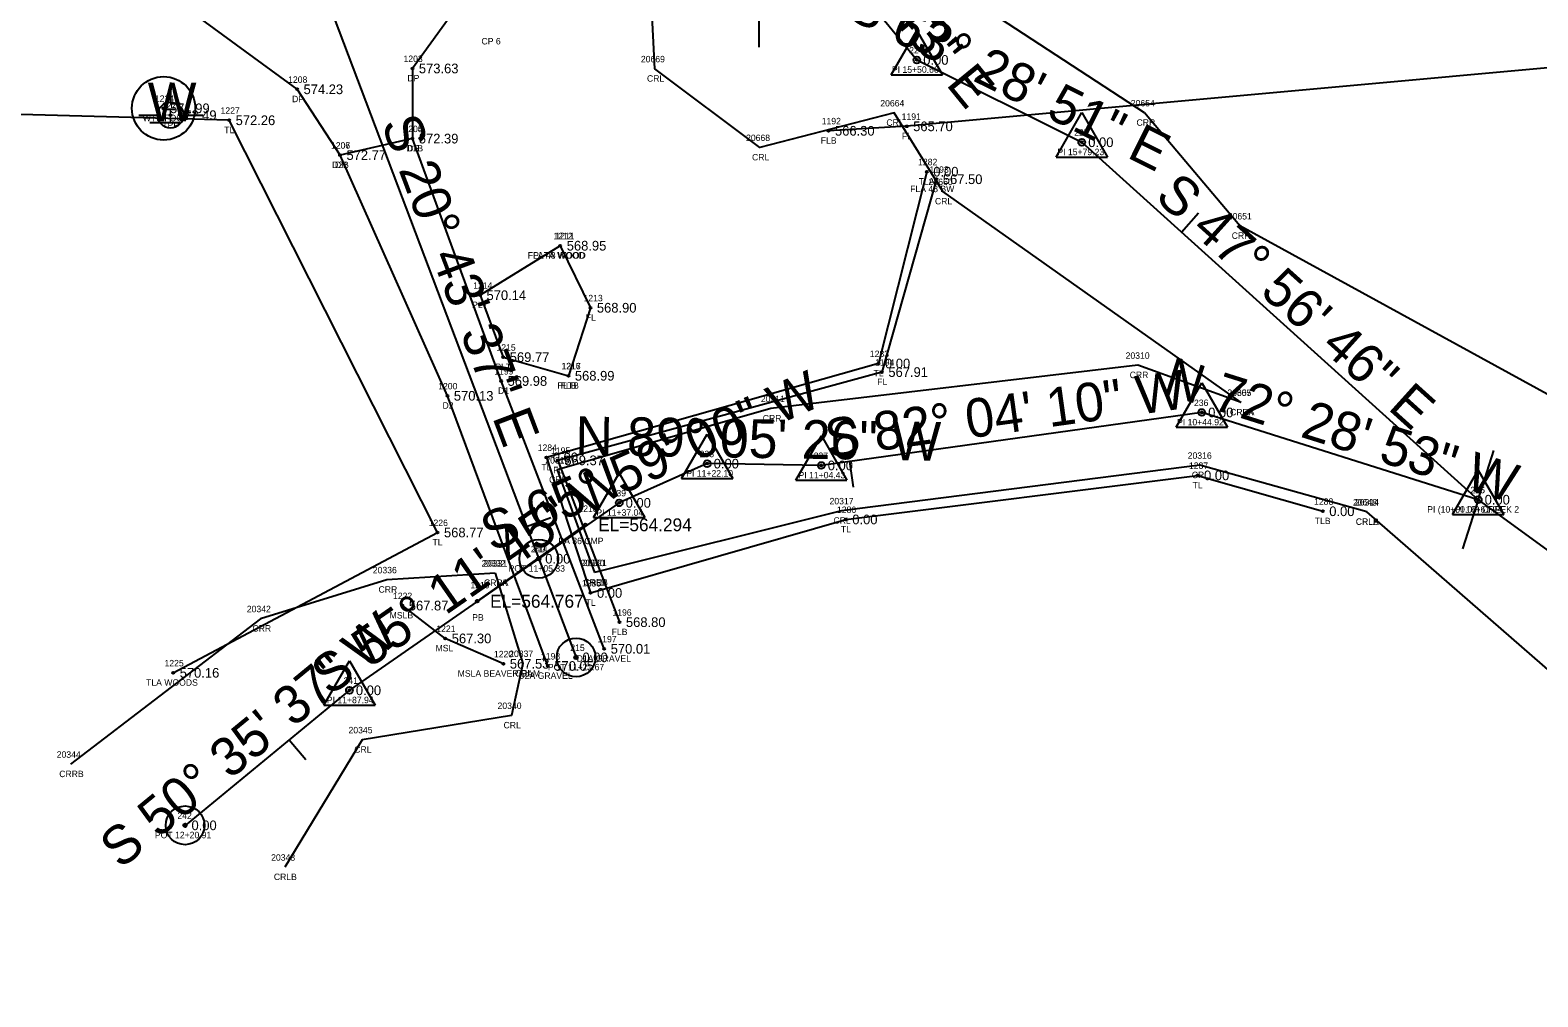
# Model space of a CAD drawing. Extents: x 1529475 to 1532053, y 876698 to 877911.
# Drawn here: x 1530784.5 to 1531018, y 877104.3 to 877254.2 of the extents above; entities that cross this region are included whole.
import ezdxf

# ---------------------------------------------------------------- set-up
doc = ezdxf.new("R2010")
doc.units = 0
for name, color, linetype in [('RD_EX_BldgApp', 7, 'Continuous'), ('RD_EX_BldgApp_txCode', 7, 'Continuous'), ('RD_EX_DR_Pipe', 7, 'Continuous'), ('RD_EX_DR_Pipe_txCode', 7, 'Continuous'), ('RD_EX_Driveway', 7, 'Continuous'), ('RD_EX_Driveway_txCode', 7, 'Continuous'), ('RD_EX_Fence_Other', 7, 'Continuous'), ('RD_EX_Fence_Other_txCode', 7, 'Continuous'), ('RD_EX_H2O', 7, 'Continuous'), ('RD_EX_H2O_txCode', 7, 'Continuous'), ('RD_EX_Misc', 7, 'Continuous'), ('RD_EX_Misc_txCode', 7, 'Continuous'), ('RD_EX_TX_BldgApp_ELEV', 7, 'Continuous'), ('RD_EX_TX_Driveway_ELEV', 7, 'Continuous'), ('RD_EX_TX_Fence_Other_ELEV', 7, 'Continuous'), ('RD_EX_TX_Misc_ELEV', 7, 'Continuous'), ('RD_EX_TX_UT_ELEV', 7, 'Continuous'), ('RD_EX_TX_VEG_ELEV', 7, 'Continuous'), ('RD_EX_UT', 7, 'Continuous'), ('RD_EX_UT_txCode', 7, 'Continuous'), ('RD_EX_VEG', 7, 'Continuous'), ('RD_EX_VEG_txCode', 7, 'Continuous'), ('RD_HC_Cl', 7, 'Continuous'), ('RD_HC_Data', 7, 'Continuous'), ('RD_HC_Data_Tic', 7, 'Continuous'), ('RD_HC_Survey_ELEV', 7, 'Continuous'), ('RD_HC_Survey_txCode', 7, 'Continuous'), ('RD_HC_txCode', 7, 'Continuous'), ('RD_SMD_Locator', 7, 'Continuous'), ('RD_TX_Pipe_ElevEX', 7, 'Continuous')]:
    doc.layers.add(name, color=color, linetype=linetype)

msp = doc.modelspace()

# ---------------------------------------------------------------- linework, layer by layer
at = {"layer": 'RD_EX_BldgApp'}
msp.add_lwpolyline([(1530866.59, 877220.77), (1530854.16, 877213.09), (1530857.76, 877203.5), (1530867.85, 877200.61)], dxfattribs=at)
at = {"layer": 'RD_EX_DR_Pipe'}
msp.add_line((1530870.46, 877177.51), (1530853.72, 877165.66), dxfattribs=at)
at = {"layer": 'RD_EX_Driveway'}
for points in [[(1530852.87, 877260.97), (1530843.68, 877248.24), (1530843.67, 877237.37), (1530832.46, 877234.81), (1530825.81, 877245.01), (1530806.23, 877259.4)], [(1530873.4, 877158.29), (1530857.42, 877199.8), (1530843.67, 877237.37)], [(1530864.66, 877155.63), (1530849.1, 877197.5), (1530832.46, 877234.81)]]:
    msp.add_lwpolyline(points, dxfattribs=at)
at = {"layer": 'RD_EX_Fence_Other'}
for points in [[(1531584.5, 877106.78), (1531547.82, 877137.37), (1531457.58, 877185.31), (1531406.02, 877209.64), (1531373.66, 877220.15), (1531357.95, 877224.14), (1531321.76, 877233.71), (1531272.23, 877245.59), (1531232.6, 877249.66), (1531180.73, 877254.11), (1531131.27, 877254.15), (1531075.59, 877251.89), (1531032.65, 877249.5), (1530920.26, 877239.27), (1530908.15, 877238.58)], [(1530924.86, 877231.07), (1530916.42, 877201.18), (1530866.22, 877187.5), (1530875.76, 877162.42)], [(1530866.59, 877220.77), (1530871.26, 877211.15), (1530867.85, 877200.61)]]:
    msp.add_lwpolyline(points, dxfattribs=at)
at = {"layer": 'RD_EX_H2O'}
msp.add_line((1530897.4, 877251.52), (1530897.4, 877261.52), dxfattribs=at)
for points in [[(1531030.35, 877191.82), (1530971.87, 877223.83), (1530957.12, 877241.36), (1530927.2, 877260.93), (1530922.5, 877289.86), (1530895.04, 877301.24), (1530872.88, 877333.85), (1530860.22, 877363.17), (1530828.43, 877393.28), (1530808.3, 877433.62), (1530784.24, 877462.07), (1530773.36, 877492.12), (1530746.47, 877535.88), (1530723.52, 877580.98), (1530706.2, 877619.34), (1530689.1, 877649.27), (1530633.62, 877702.51)], [(1530972.1, 877196.48), (1530925.87, 877229.17), (1530918.34, 877241.35), (1530897.53, 877235.99), (1530881.25, 877248.19), (1530880.72, 877258.4), (1530879.1, 877290.18), (1530865.94, 877309.23), (1530832.49, 877347.64), (1530816.44, 877373.18)], [(1530972.1, 877196.48), (1530956.06, 877202.24), (1530899.21, 877195.52), (1530866.11, 877186.01), (1530871.9, 877170.1)], [(1530991.55, 877179.5), (1530965.66, 877186.74), (1530910.14, 877179.68), (1530871.9, 877170.1)], [(1531352.2, 877088.06), (1531314.99, 877102.13), (1531274.47, 877089.9), (1531245.67, 877076.46), (1531215.61, 877089.16), (1531183.19, 877108.46), (1531131.31, 877133.17), (1531102.07, 877130.33), (1531078.17, 877119.78), (1531028.38, 877147.46), (1530991.55, 877179.5)], [(1530856.5, 877170.04), (1530839.69, 877168.99), (1530820.14, 877162.96), (1530790.69, 877140.4)], [(1530856.5, 877170.04), (1530860.79, 877156.02), (1530859.03, 877147.96), (1530835.9, 877144.19), (1530823.91, 877124.45)]]:
    msp.add_lwpolyline(points, dxfattribs=at)
at = {"layer": 'RD_EX_Misc'}
msp.add_lwpolyline([(1530857.77, 877155.97), (1530848.77, 877159.9), (1530842.12, 877164.99)], dxfattribs=at)
at = {"layer": 'RD_EX_UT'}
for p, q in [((1530806.2, 877246.07), (1530806.2, 877243)), ((1530801.27, 877241.01), (1530804.2, 877241.01)), ((1530808.2, 877241.01), (1530811.27, 877241.01)), ((1530803, 877239.85), (1530807.63, 877239.85))]:
    msp.add_line(p, q, dxfattribs=at)
for centre, radius in [((1530805.13, 877242.06), 4.91), ((1530806.2, 877241), 2)]:
    msp.add_circle(centre, radius, dxfattribs=at)
at = {"layer": 'RD_EX_VEG'}
for points in [[(1530806.62, 877154.57), (1530847.57, 877176.32), (1530815.29, 877240.21), (1530607.98, 877245.85), (1530502.71, 877258.91), (1530344.51, 877291.95), (1530315.54, 877291.5), (1530341.13, 877248.83)], [(1530923.38, 877232.24), (1530915.9, 877202.51), (1530864.43, 877187.96), (1530871.28, 877166.95), (1530910.83, 877178.34), (1530965.33, 877185.17), (1530984.73, 877179.61)]]:
    msp.add_lwpolyline(points, dxfattribs=at)
at = {"layer": 'RD_HC_Cl'}
for p, q in [((1530901.97, 877273.85), (1530921.83, 877249.56)), ((1530825.97, 877270.76), (1530869.03, 877156.96)), ((1530921.83, 877249.56), (1530947.39, 877236.8)), ((1530947.39, 877236.8), (1531008.81, 877181.4)), ((1530965.97, 877194.92), (1530907.03, 877186.71)), ((1531008.81, 877181.4), (1530965.97, 877194.92)), ((1530889.36, 877186.99), (1530875.72, 877180.91)), ((1530907.03, 877186.71), (1530889.36, 877186.99)), ((1530875.72, 877180.91), (1530833.92, 877151.86)), ((1531008.81, 877181.4), (1531075.6, 877132.71)), ((1530833.92, 877151.86), (1530808.45, 877130.93))]:
    msp.add_line(p, q, dxfattribs=at)
at = {"layer": 'RD_HC_Data'}
for p, q in [((1530917.86, 877247.26), (1530921.84, 877254.14)), ((1530921.84, 877254.14), (1530925.8, 877247.26)), ((1530917.86, 877247.26), (1530925.8, 877247.26)), ((1530943.42, 877234.51), (1530947.39, 877241.39)), ((1530947.39, 877241.39), (1530951.36, 877234.51)), ((1530943.42, 877234.51), (1530951.36, 877234.51)), ((1530962, 877192.63), (1530965.97, 877199.51)), ((1530965.97, 877199.51), (1530969.94, 877192.63)), ((1530962, 877192.63), (1530969.94, 877192.63)), ((1530885.39, 877184.7), (1530889.36, 877191.58)), ((1530889.36, 877191.58), (1530893.33, 877184.7)), ((1530903.06, 877184.42), (1530907.04, 877191.3)), ((1530907.04, 877191.3), (1530911, 877184.42)), ((1530871.75, 877178.62), (1530875.72, 877185.5)), ((1530875.72, 877185.5), (1530879.69, 877178.62)), ((1530885.39, 877184.7), (1530893.33, 877184.7)), ((1531004.84, 877179.11), (1531008.81, 877185.99)), ((1531004.84, 877179.11), (1531008.81, 877185.99)), ((1531008.81, 877185.99), (1531012.78, 877179.11)), ((1531008.81, 877185.99), (1531012.78, 877179.11)), ((1530903.06, 877184.42), (1530911, 877184.42)), ((1530871.75, 877178.62), (1530879.69, 877178.62)), ((1531004.84, 877179.11), (1531012.78, 877179.11)), ((1531004.84, 877179.11), (1531012.78, 877179.11)), ((1530829.95, 877149.56), (1530833.92, 877156.44)), ((1530833.92, 877156.44), (1530837.89, 877149.56)), ((1530829.95, 877149.56), (1530837.89, 877149.56))]:
    msp.add_line(p, q, dxfattribs=at)
for centre, radius in [((1530921.83, 877249.56), 0.529), ((1530947.39, 877236.8), 0.529), ((1530965.97, 877194.92), 0.529), ((1530889.36, 877186.99), 0.529), ((1530907.03, 877186.71), 0.529), ((1530875.72, 877180.91), 0.529), ((1531008.81, 877181.4), 0.529), ((1531008.81, 877181.4), 0.529), ((1530863.25, 877172.25), 3), ((1530863.25, 877172.25), 3), ((1530863.25, 877172.25), 0.282), ((1530863.25, 877172.25), 0.282), ((1530869.03, 877156.96), 3), ((1530869.03, 877156.96), 0.282), ((1530833.92, 877151.86), 0.529), ((1530808.45, 877130.93), 3), ((1530808.45, 877130.93), 0.282)]:
    msp.add_circle(centre, radius, dxfattribs=at)
at = {"layer": 'RD_HC_Data_Tic'}
for p, q in [((1530962.82, 877222.89), (1530965.49, 877225.86)), ((1530911.42, 877187.32), (1530911.97, 877183.36)), ((1531008.81, 877181.4), (1531011.22, 877189.03)), ((1531008.81, 877181.4), (1531006.4, 877173.77)), ((1530861.36, 877177.23), (1530865.1, 877178.64)), ((1530824.6, 877144.2), (1530827.14, 877141.11))]:
    msp.add_line(p, q, dxfattribs=at)
at = {"layer": 'RD_SMD_Locator'}
for centre, radius in [((1530843.68, 877248.24), 0.15), ((1530921.83, 877249.56), 0.15), ((1530825.81, 877245.01), 0.15), ((1530805.13, 877242.06), 0.15), ((1530806.2, 877241), 0.15), ((1530815.29, 877240.21), 0.15), ((1530908.15, 877238.58), 0.15), ((1530920.26, 877239.27), 0.15), ((1530843.67, 877237.37), 0.15), ((1530843.67, 877237.37), 0.15), ((1530947.39, 877236.8), 0.15), ((1530832.46, 877234.81), 0.15), ((1530832.46, 877234.81), 0.15), ((1530923.38, 877232.24), 0.15), ((1530924.86, 877231.07), 0.15), ((1530866.59, 877220.77), 0.15), ((1530866.59, 877220.77), 0.15), ((1530854.16, 877213.09), 0.15), ((1530871.26, 877211.15), 0.15), ((1530857.76, 877203.5), 0.15), ((1530915.9, 877202.51), 0.15), ((1530916.42, 877201.18), 0.15), ((1530857.42, 877199.8), 0.15), ((1530867.85, 877200.61), 0.15), ((1530867.85, 877200.61), 0.15), ((1530849.1, 877197.5), 0.15), ((1530965.97, 877194.92), 0.15), ((1530864.43, 877187.96), 0.15), ((1530866.22, 877187.5), 0.15), ((1530889.36, 877186.99), 0.15), ((1530907.03, 877186.71), 0.15), ((1530965.33, 877185.17), 0.15), ((1530875.72, 877180.91), 0.15), ((1531008.81, 877181.4), 0.15), ((1531008.81, 877181.4), 0.15), ((1530870.46, 877177.51), 0.2), ((1530910.83, 877178.34), 0.15), ((1530984.73, 877179.61), 0.15), ((1530847.57, 877176.32), 0.15), ((1530863.25, 877172.25), 0.15), ((1530863.25, 877172.25), 0.15), ((1530871.28, 877166.95), 0.15), ((1530842.12, 877164.99), 0.15), ((1530853.72, 877165.66), 0.2), ((1530875.76, 877162.42), 0.15), ((1530848.77, 877159.9), 0.15), ((1530869.03, 877156.96), 0.15), ((1530873.4, 877158.29), 0.15), ((1530806.62, 877154.57), 0.15), ((1530857.77, 877155.97), 0.15), ((1530864.66, 877155.63), 0.15), ((1530833.92, 877151.86), 0.15), ((1530808.45, 877130.93), 0.15)]:
    msp.add_circle(centre, radius, dxfattribs=at)

# ---------------------------------------------------------------- texts
at = {"layer": 'RD_EX_BldgApp_txCode'}
for s, p in [('1212', (1530865.53, 877221.77)), ('PLTA WOOD', (1530862.39, 877218.77)), ('1214', (1530853.1, 877214.09)), ('PLT', (1530852.92, 877211.09)), ('1215', (1530856.7, 877204.5)), ('PLT', (1530856.52, 877201.5)), ('1216', (1530866.76, 877201.61)), ('PLTB', (1530866.13, 877198.61))]:
    msp.add_text(s, height=1, dxfattribs=at).set_placement(p)
at = {"layer": 'RD_EX_DR_Pipe_txCode'}
for s, p in [('1218', (1530869.4, 877179.51)), ('PA 36 CMP', (1530866.3, 877174.51)), ('1219', (1530852.66, 877167.66)), ('PB', (1530852.94, 877162.66))]:
    msp.add_text(s, height=1, dxfattribs=at).set_placement(p)
at = {"layer": 'RD_EX_Driveway_txCode'}
for s, p in [('1203', (1530842.3, 877249.24)), ('1208', (1530824.42, 877246.01)), ('DP', (1530842.9, 877246.24)), ('DP', (1530825.03, 877243.01)), ('1204', (1530842.29, 877238.37)), ('1205', (1530842.29, 877238.37)), ('1206', (1530831.05, 877235.81)), ('1207', (1530831.07, 877235.81)), ('D1B', (1530842.73, 877235.37)), ('DP', (1530842.89, 877235.37)), ('D2B', (1530831.23, 877232.81)), ('DP', (1530831.68, 877232.81)), ('1199', (1530856.36, 877200.8)), ('1200', (1530847.67, 877198.5)), ('D1', (1530856.95, 877197.8)), ('D2', (1530848.34, 877195.5)), ('1197', (1530872.34, 877159.29)), ('1198', (1530863.6, 877156.63)), ('D1A GRAVEL', (1530869.14, 877156.29)), ('D2A GRAVEL', (1530860.11, 877153.63))]:
    msp.add_text(s, height=1, dxfattribs=at).set_placement(p)
at = {"layer": 'RD_EX_Fence_Other_txCode'}
for s, p in [('1191', (1530919.48, 877240.27)), ('1192', (1530907.09, 877239.58)), ('FLB', (1530906.95, 877236.58)), ('FL', (1530919.53, 877237.27)), ('1193', (1530923.8, 877232.07)), ('FLA 48 BW', (1530920.8, 877229.07)), ('1211', (1530865.81, 877221.77)), ('FLA 48 WOOD', (1530861.55, 877218.77)), ('1213', (1530870.19, 877212.15)), ('FL', (1530870.53, 877209.15)), ('1217', (1530866.79, 877201.61)), ('1194', (1530915.36, 877202.18)), ('FLB', (1530866.65, 877198.61)), ('FL', (1530915.69, 877199.18)), ('1195', (1530865.16, 877188.5)), ('FL', (1530865.49, 877185.5)), ('1196', (1530874.67, 877163.42)), ('FLB', (1530874.55, 877160.42))]:
    msp.add_text(s, height=1, dxfattribs=at).set_placement(p)
at = {"layer": 'RD_EX_H2O_txCode'}
for s, p in [('20669', (1530879.08, 877249.19)), ('CRL', (1530880.02, 877246.19)), ('20664', (1530916.17, 877242.35)), ('20654', (1530954.98, 877242.36)), ('CRL', (1530917.11, 877239.35)), ('CRR', (1530955.87, 877239.36)), ('20668', (1530895.37, 877236.99)), ('CRL', (1530896.3, 877233.99)), ('20660', (1530923.66, 877230.17)), ('CRL', (1530924.64, 877227.17)), ('20651', (1530970.01, 877224.83)), ('CRR', (1530970.62, 877221.83)), ('20310', (1530954.18, 877203.24)), ('CRR', (1530954.81, 877200.24)), ('20311', (1530897.66, 877196.52)), ('20307', (1530969.94, 877197.48)), ('20655', (1530969.95, 877197.48)), ('CRR', (1530897.96, 877193.52)), ('CRRA', (1530970.35, 877194.48)), ('CRLA', (1530970.38, 877194.48)), ('20313', (1530864.27, 877187.01)), ('20316', (1530963.8, 877187.74)), ('CRR', (1530864.85, 877184.01)), ('CRL', (1530964.43, 877184.74)), ('20317', (1530908.31, 877180.68)), ('20648', (1530989.41, 877180.5)), ('20314', (1530989.71, 877180.5)), ('CRL', (1530908.91, 877177.68)), ('CRLA', (1530989.83, 877177.5)), ('CRLB', (1530989.85, 877177.5)), ('20336', (1530837.54, 877169.99)), ('20332', (1530854.38, 877171.04)), ('20331', (1530854.66, 877171.04)), ('20320', (1530869.74, 877171.1)), ('20321', (1530870.07, 877171.1)), ('CRRA', (1530854.76, 877168.04)), ('CRLA', (1530854.78, 877168.04)), ('CRRB', (1530870.18, 877168.1)), ('CRLB', (1530870.2, 877168.1)), ('CRR', (1530838.43, 877166.99)), ('20342', (1530818.02, 877163.96)), ('CRR', (1530818.89, 877160.96)), ('20337', (1530858.67, 877157.02)), ('CRL', (1530859.56, 877154.02)), ('20340', (1530856.87, 877148.96)), ('20345', (1530833.78, 877145.19)), ('CRL', (1530857.8, 877145.96)), ('CRL', (1530834.67, 877142.19)), ('20344', (1530788.57, 877141.4)), ('CRRB', (1530788.96, 877138.4)), ('20348', (1530821.79, 877125.45)), ('CRLB', (1530822.21, 877122.45))]:
    msp.add_text(s, height=1, dxfattribs=at).set_placement(p)
at = {"layer": 'RD_EX_Misc_txCode'}
for s, p in [('1222', (1530840.67, 877165.99)), ('MSLB', (1530840.15, 877162.99)), ('1221', (1530847.38, 877160.9)), ('MSL', (1530847.26, 877157.9)), ('1220', (1530856.31, 877156.97)), ('MSLA BEAVER DAM', (1530850.69, 877153.97))]:
    msp.add_text(s, height=1, dxfattribs=at).set_placement(p)
at = {"layer": 'RD_EX_TX_BldgApp_ELEV'}
for s, p in [('568.95', (1530867.59, 877220.02)), ('570.14', (1530855.16, 877212.34)), ('569.77', (1530858.76, 877202.75)), ('568.99', (1530868.85, 877199.86))]:
    msp.add_text(s, height=1.5, dxfattribs=at).set_placement(p)
at = {"layer": 'RD_EX_TX_Driveway_ELEV'}
for s, p in [('573.63', (1530844.68, 877247.49)), ('574.23', (1530826.81, 877244.26)), ('572.39', (1530844.67, 877236.62)), ('572.39', (1530844.67, 877236.62)), ('572.77', (1530833.46, 877234.06)), ('572.77', (1530833.46, 877234.06)), ('569.98', (1530858.42, 877199.05)), ('570.13', (1530850.1, 877196.75)), ('570.01', (1530874.4, 877157.54)), ('570.05', (1530865.66, 877154.88))]:
    msp.add_text(s, height=1.5, dxfattribs=at).set_placement(p)
at = {"layer": 'RD_EX_TX_Fence_Other_ELEV'}
for s, p in [('566.30', (1530909.15, 877237.83)), ('565.70', (1530921.26, 877238.52)), ('567.50', (1530925.86, 877230.32)), ('568.95', (1530867.59, 877220.02)), ('568.90', (1530872.26, 877210.4)), ('568.99', (1530868.85, 877199.86)), ('567.91', (1530917.42, 877200.43)), ('569.37', (1530867.22, 877186.75)), ('568.80', (1530876.76, 877161.67))]:
    msp.add_text(s, height=1.5, dxfattribs=at).set_placement(p)
at = {"layer": 'RD_EX_TX_Misc_ELEV'}
for s, p in [('567.87', (1530843.12, 877164.24)), ('567.30', (1530849.77, 877159.15)), ('567.53', (1530858.77, 877155.22))]:
    msp.add_text(s, height=1.5, dxfattribs=at).set_placement(p)
at = {"layer": 'RD_EX_TX_UT_ELEV'}
for s, p in [('571.99', (1530806.13, 877241.31)), ('572.49', (1530807.2, 877240.25))]:
    msp.add_text(s, height=1.5, dxfattribs=at).set_placement(p)
at = {"layer": 'RD_EX_TX_VEG_ELEV'}
for s, p in [('572.26', (1530816.29, 877239.46)), ('0.00', (1530924.38, 877231.49)), ('0.00', (1530916.9, 877201.76)), ('0.00', (1530865.43, 877187.21)), ('0.00', (1530966.33, 877184.42)), ('0.00', (1530985.73, 877178.86)), ('0.00', (1530911.83, 877177.59)), ('568.77', (1530848.57, 877175.57)), ('0.00', (1530872.28, 877166.2)), ('570.16', (1530807.62, 877153.82))]:
    msp.add_text(s, height=1.5, dxfattribs=at).set_placement(p)
at = {"layer": 'RD_EX_UT'}
for s, height, p in [('W', 6, (1530802.66, 877240.06)), ('T', 2, (1530805.35, 877239.95))]:
    msp.add_text(s, height=height, dxfattribs=at).set_placement(p)
at = {"layer": 'RD_EX_UT_txCode'}
for s, p in [('1224', (1530803.78, 877243.06)), ('WTS FOC', (1530801.91, 877240.06)), ('1223', (1530804.86, 877242)), ('TPP', (1530804.93, 877239))]:
    msp.add_text(s, height=1, dxfattribs=at).set_placement(p)
at = {"layer": 'RD_EX_VEG_txCode'}
for s, p in [('1227', (1530813.95, 877241.21)), ('TL', (1530814.52, 877238.21)), ('1282', (1530922.03, 877233.24)), ('TLA', (1530922.12, 877230.24)), ('1283', (1530914.55, 877203.51)), ('TL', (1530915.13, 877200.51)), ('1284', (1530863.09, 877188.96)), ('1287', (1530963.99, 877186.17)), ('TL', (1530863.66, 877185.96)), ('TL', (1530964.56, 877183.17)), ('1286', (1530909.46, 877179.34)), ('1288', (1530983.38, 877180.61)), ('1226', (1530846.2, 877177.32)), ('TLB', (1530983.48, 877177.61)), ('TL', (1530910.06, 877176.34)), ('TL', (1530846.79, 877174.32)), ('1285', (1530869.93, 877167.95)), ('TL', (1530870.51, 877164.95)), ('1225', (1530805.27, 877155.57)), ('TLA WOODS', (1530802.41, 877152.57))]:
    msp.add_text(s, height=1, dxfattribs=at).set_placement(p)
at = {"layer": 'RD_HC_Data'}
for s, rotation, p in [('S 39%%d 15\' 43" E', 309.262, (1530895.44, 877283.43)), ('S 63%%d 28\' 51" E', 333.4808, (1530910.68, 877256.24)), ('S 20%%d 43\' 37" E', 290.7269, (1530838.8, 877239.69)), ('S 47%%d 56\' 46" E', 317.9461, (1530958.54, 877228.09)), ('N 72%%d 28\' 53" W', 342.4813, (1530959.73, 877197.94)), ('S 65%%d 59\' 00" W', 24.0165, (1530856.02, 877173.23)), ('S 82%%d 04\' 10" W', 7.9305, (1530908.05, 877187.86)), ('N 89%%d 05\' 26" W', 359.0906, (1530868.89, 877188.32)), ('S 55%%d 11\' 45" W', 34.8041, (1530830.78, 877150.89)), ('S 50%%d 35\' 37" W', 39.4063, (1530798.46, 877124.02))]:
    msp.add_text(s, height=6, rotation=rotation, dxfattribs=at).set_placement(p)
at = {"layer": 'RD_HC_Survey_ELEV'}
for p in [(1530922.83, 877248.81), (1530948.39, 877236.05), (1530966.97, 877194.17), (1530890.36, 877186.24), (1530908.03, 877185.96), (1530876.72, 877180.16), (1531009.81, 877180.65), (1531009.81, 877180.65), (1530864.25, 877171.5), (1530864.25, 877171.5), (1530870.03, 877156.21), (1530834.92, 877151.11), (1530809.45, 877130.18)]:
    msp.add_text('0.00', height=1.5, dxfattribs=at).set_placement(p)
at = {"layer": 'RD_HC_Survey_txCode'}
msp.add_text('CP 6', height=1, dxfattribs=at).set_placement((1530854.38, 877251.96))
at = {"layer": 'RD_HC_txCode'}
for s, p in [('224', (1530920.65, 877250.56)), ('PI 15+50.66', (1530917.97, 877247.56)), ('225', (1530946.21, 877237.8)), ('PI 15+79.23', (1530943.61, 877234.8)), ('236', (1530964.77, 877195.92)), ('PI 10+44.92', (1530962.15, 877192.92)), ('238', (1530888.18, 877187.99)), ('237', (1530905.85, 877187.71)), ('PI 11+22.10', (1530886.11, 877184.99)), ('PI 11+04.43', (1530903.5, 877184.71)), ('239', (1530874.54, 877181.91)), ('226', (1531007.6, 877182.4)), ('235', (1531007.63, 877182.4)), ('PI (10+00.00) CREEK 2', (1531000.91, 877179.4)), ('PI 16+61.94', (1531005.26, 877179.4)), ('PI 11+37.04', (1530872.18, 877178.91)), ('240', (1530862.03, 877173.25)), ('214', (1530862.35, 877173.25)), ('POT 11+05.33', (1530858.58, 877170.25)), ('POT 11+05.33', (1530858.58, 877170.25)), ('215', (1530868.14, 877157.96)), ('POT 11+21.67', (1530864.66, 877154.96)), ('241', (1530833.02, 877152.86)), ('PI 11+87.94', (1530830.42, 877149.86)), ('242', (1530807.27, 877131.93)), ('POT 12+20.91', (1530803.78, 877128.93))]:
    msp.add_text(s, height=1, dxfattribs=at).set_placement(p)
at = {"layer": 'RD_TX_Pipe_ElevEX'}
for s, p in [('EL=564.294', (1530872.46, 877176.51)), ('EL=564.767', (1530855.72, 877164.66))]:
    msp.add_text(s, height=2, dxfattribs=at).set_placement(p)

doc.saveas('drawing.dxf')
